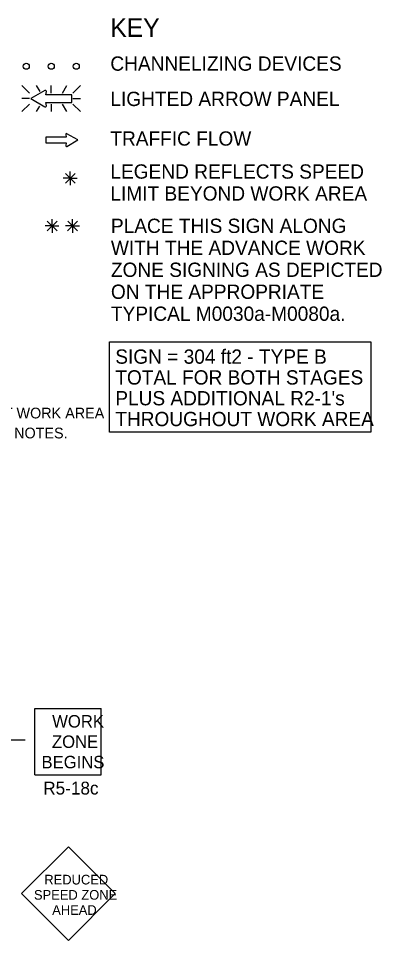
# Model space of a CAD drawing. Extents: x 16576 to 19508, y 5728 to 6974.
# Drawn here: x 17179 to 17415, y 6315 to 6915 of the extents above; entities that cross this region are included whole.
import ezdxf

# ---------------------------------------------------------------- set-up
doc = ezdxf.new("R2010")
doc.units = 0
for name, color, linetype in [('MT_SCRATCH_LEVEL_E', 7, 'Continuous'), ('TRAFFIC_SIGNS_PR', 7, 'Continuous'), ('TYPICAL_TEXT_DIMEN_EX', 7, 'Continuous'), ('TYPICAL_TEXT_DIMEN_PR', 7, 'Continuous')]:
    doc.layers.add(name, color=color, linetype=linetype)

msp = doc.modelspace()

# ---------------------------------------------------------------- linework, layer by layer
at = {"layer": 'MT_SCRATCH_LEVEL_E'}
for p, q in [((17217.37, 6836.29), (17210.13, 6840.4)), ((17209.76, 6838.14), (17196.5, 6838.14)), ((17196.5, 6838.14), (17196.5, 6834.4)), ((17196.5, 6834.4), (17209.76, 6834.4)), ((17209.44, 6839.92), (17209.76, 6838.14)), ((17209.76, 6834.4), (17209.44, 6832.62)), ((17210.13, 6832.15), (17217.37, 6836.29))]:
    msp.add_line(p, q, dxfattribs=at)
for centre, start, end in [((17209.9, 6839.99), 60.42484, 189.96381), ((17209.9, 6832.55), 170.03619, 299.77312)]:
    msp.add_arc(centre, 0.463, start, end, dxfattribs=at)
at = {"layer": 'TRAFFIC_SIGNS_PR'}
for p, q in [((17180.95, 6871.72), (17185.88, 6866.79)), ((17192.71, 6867.9), (17190.51, 6871.72)), ((17200.03, 6866.79), (17200.03, 6871.72)), ((17207.27, 6866.79), (17210.12, 6871.72)), ((17214.18, 6866.79), (17219.12, 6871.72)), ((17185.88, 6863.23), (17180.95, 6863.23)), ((17180.95, 6854.74), (17185.88, 6859.68)), ((17190.46, 6854.74), (17192.57, 6858.4)), ((17200.03, 6859.68), (17200.03, 6854.74)), ((17210.16, 6854.74), (17207.31, 6859.68)), ((17214.18, 6863.23), (17219.12, 6863.23)), ((17214.18, 6859.68), (17219.12, 6854.74)), ((17189.39, 6422.87), (17189.39, 6466.07)), ((17189.39, 6466.07), (17232.59, 6466.07)), ((17232.59, 6422.87), (17232.59, 6466.07)), ((17189.39, 6422.87), (17232.59, 6422.87)), ((17211.21, 6376), (17180.66, 6345.46)), ((17241.75, 6345.46), (17211.21, 6376)), ((17180.66, 6345.46), (17211.21, 6314.91)), ((17211.21, 6314.91), (17241.75, 6345.46))]:
    msp.add_line(p, q, dxfattribs=at)
for points in [[(17195.96, 6868.51), (17186.67, 6863.23), (17195.96, 6857.91)], [(17196.84, 6858.54), (17196.44, 6860.81), (17213.45, 6860.81), (17213.45, 6865.61), (17196.44, 6865.61), (17196.84, 6867.89)]]:
    msp.add_lwpolyline(points, dxfattribs=at)
for centre in [(17183.74, 6884.34), (17200.04, 6884.34), (17216.34, 6884.34)]:
    msp.add_circle(centre, 2, dxfattribs=at)
for centre, radius, start, end in [((17196.25, 6867.98), 0.598, 350.73078, 118.89165), ((17196.25, 6858.43), 0.597, 241.48329, 9.95933)]:
    msp.add_arc(centre, radius, start, end, dxfattribs=at)
at = {"layer": 'TYPICAL_TEXT_DIMEN_EX'}
for p, q in [((17212.44, 6811.36), (17207.91, 6811.36)), ((17209.25, 6814.55), (17215.63, 6808.17)), ((17215.63, 6814.55), (17209.25, 6808.17)), ((17212.44, 6811.36), (17212.44, 6815.82)), ((17212.44, 6811.36), (17215.63, 6811.36)), ((17212.44, 6811.36), (17216.92, 6811.36)), ((17212.44, 6811.36), (17212.44, 6806.86)), ((17200.61, 6780.3), (17196.08, 6780.3)), ((17197.42, 6783.48), (17203.8, 6777.11)), ((17203.8, 6783.48), (17197.42, 6777.11)), ((17200.61, 6780.3), (17200.61, 6784.75)), ((17200.61, 6780.3), (17203.8, 6780.3)), ((17200.61, 6780.3), (17205.09, 6780.3)), ((17200.61, 6780.3), (17200.61, 6775.8)), ((17213.93, 6780.3), (17209.4, 6780.3)), ((17217.12, 6783.48), (17210.74, 6777.11)), ((17210.75, 6783.48), (17217.12, 6777.11)), ((17213.93, 6780.3), (17213.93, 6784.75)), ((17213.93, 6780.3), (17217.12, 6780.3)), ((17213.93, 6780.3), (17218.41, 6780.3)), ((17213.93, 6780.3), (17213.93, 6775.8))]:
    msp.add_line(p, q, dxfattribs=at)
msp.add_lwpolyline([(17238.08, 6704.81), (17408.44, 6704.81), (17408.44, 6646.06), (17238.08, 6646.06)], close=True, dxfattribs=at)
at = {"layer": 'TYPICAL_TEXT_DIMEN_PR'}
msp.add_line((17037.77, 6445.62), (17183, 6445.62), dxfattribs=at)

# ---------------------------------------------------------------- texts
at = {"layer": 'TRAFFIC_SIGNS_PR'}
for s, height, p in [('PLACE THROUGHOUT WORK AREA', 7, (17074.43, 6654.95)), ('AS INDICATED IN THE NOTES.', 7, (17074.43, 6641.95)), ('WORK', 8.119, (17200.64, 6453.65)), ('ZONE', 8.119, (17200.5, 6440.37)), ('BEGINS', 8.119, (17193.67, 6427.08)), ('R5-18c', 8.37, (17194.8, 6410)), ('REDUCED', 6.3, (17195.52, 6351.43)), ('SPEED ZONE', 6.3, (17188.76, 6341.53)), ('AHEAD', 6.3, (17200.64, 6331.63))]:
    msp.add_text(s, height=height, dxfattribs=at).set_placement(p)
at = {"layer": 'TYPICAL_TEXT_DIMEN_EX'}
for s, height, p in [('KEY', 12, (17238.58, 6903.45)), ('CHANNELIZING DEVICES', 9.31, (17238.58, 6881.4)), ('LIGHTED ARROW PANEL', 9.31, (17238.58, 6858.4)), ('TRAFFIC FLOW', 9.3, (17238.58, 6832.61)), ('LEGEND REFLECTS SPEED', 9.31, (17238.58, 6811.11)), ('LIMIT BEYOND WORK AREA', 9.31, (17238.58, 6796.8)), ('PLACE THIS SIGN ALONG', 9.31, (17238.94, 6775.74)), ('WITH THE ADVANCE WORK', 9.31, (17238.94, 6761.43)), ('ZONE SIGNING AS DEPICTED', 9.31, (17238.94, 6747.12)), ('ON THE APPROPRIATE', 9.31, (17238.94, 6732.81)), ('TYPICAL M0030a-M0080a.', 9.31, (17238.94, 6718.5)), ('SIGN = 304 ft2 - TYPE B', 9.3, (17241.8, 6690.57)), ('TOTAL FOR BOTH STAGES', 9.3, (17241.8, 6677.02)), ("PLUS ADDITIONAL R2-1's", 9.3, (17241.8, 6663.47)), ('THROUGHOUT WORK AREA', 9.3, (17241.8, 6649.92))]:
    msp.add_text(s, height=height, dxfattribs=at).set_placement(p)

doc.saveas('drawing.dxf')
